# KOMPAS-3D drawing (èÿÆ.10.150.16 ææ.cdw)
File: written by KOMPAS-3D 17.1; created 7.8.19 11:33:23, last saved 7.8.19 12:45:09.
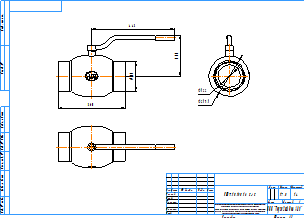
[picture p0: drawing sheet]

Sheet 1: A3, landscape

Title block, sheet 1: name: КШТ.10.150.16 С/С; material: Сталь 20  ГОСТ 1050-2013; mass: 17,8; sheets: 1; sheet format: A3; stored path: C:\Users\kka\KOMPAS_Work\Модели кранов для исследований\DN125\КШТ.10.125.16 СС.cdw

Views: Вид 1, Проекционный вид 2, Проекционный вид 3
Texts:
  kka
  adl
  Рама для чертежей
  Лит-Масса-Масштаб
  Материал-Предприятие
  Масштаб
  Изм.
  Лист
  № докум.
  Подп.
  Дата
  Лит.
  Разраб.
  Пров.
  Т.контр.
  Листов
  Внимание! Данный продукт является объектом авторского права ООО «Торговый Дом АДЛ».
  Запрещается изменение, копирование, распространение
  (в том числе путем копирования на другие сайты и ресурсы в Интернете)
  или любое иное использование информации и объектов без предварительного
  согласия правообладателя (ООО «Торговый Дом АДЛ»).
  Н.контр.
  Утв.
  ООО "Торговый дом АДЛ"
  Изменение
  Номер документа
  Подпись
  Обозначение документа
  Наименование изделия
  Масса изделия по ГОСТ 2.109-73
  Порядковый номер листа
  Общее количество листов в документе
  Характер работы, выполненной лицом, подписавшим документ
  Наименование или индекс предприятия, выпускающего документ
  Инв. № подл.
  Подп. и дата
  Взам. инв. №
  Инв. № дубл.
  Инвентарный номер подлинника по ГОСТ 2.501-68
  Подпись принявшего подлинник в отдел технической документации
  Инвентарный номер подлинника, взамен которого выпущен данный подлинник
  Инвентарный номер дубликата по ГОСТ 2.502-68
  Подпись принявшего дубликат в отдел технической документации
  Справ. №
  Перв. примен.
  Обозначение документа, взамен или на основании которого выпущен данный документ
  Обозначение документа, в котором впервые записан данный документ
  Подпись лица, копировавшего чертеж
  Обозначение формата листа
  !Рама для чертежа
Dimensions and other numbers on the sheet: 159; 360; 443; 220; 122; 219,1; 1:4; 1; 17,8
